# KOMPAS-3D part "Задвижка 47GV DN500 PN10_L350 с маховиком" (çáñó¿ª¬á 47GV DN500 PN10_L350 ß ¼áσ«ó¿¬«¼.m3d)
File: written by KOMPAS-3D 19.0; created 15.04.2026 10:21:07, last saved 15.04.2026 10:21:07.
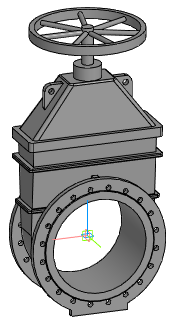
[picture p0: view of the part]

Document properties: Автор: Евгений; Полное имя файла: Z:\3.Личные\kachalov\3d для проектировщиков\2.1 Тип 47GV, 47GV.Z\Задвижка 47GV_DN40-DN600\stp_Задвижка 47GV\Задвижка 47GV DN500 PN10_L350 с маховиком.m3d

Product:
- Part/product: Задвижка 47GV DN500 PN10_L350 с маховиком

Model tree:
1. Операция без истории:1  (labels: Задвижка 47GV DN500 PN10_L350 с маховиком)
